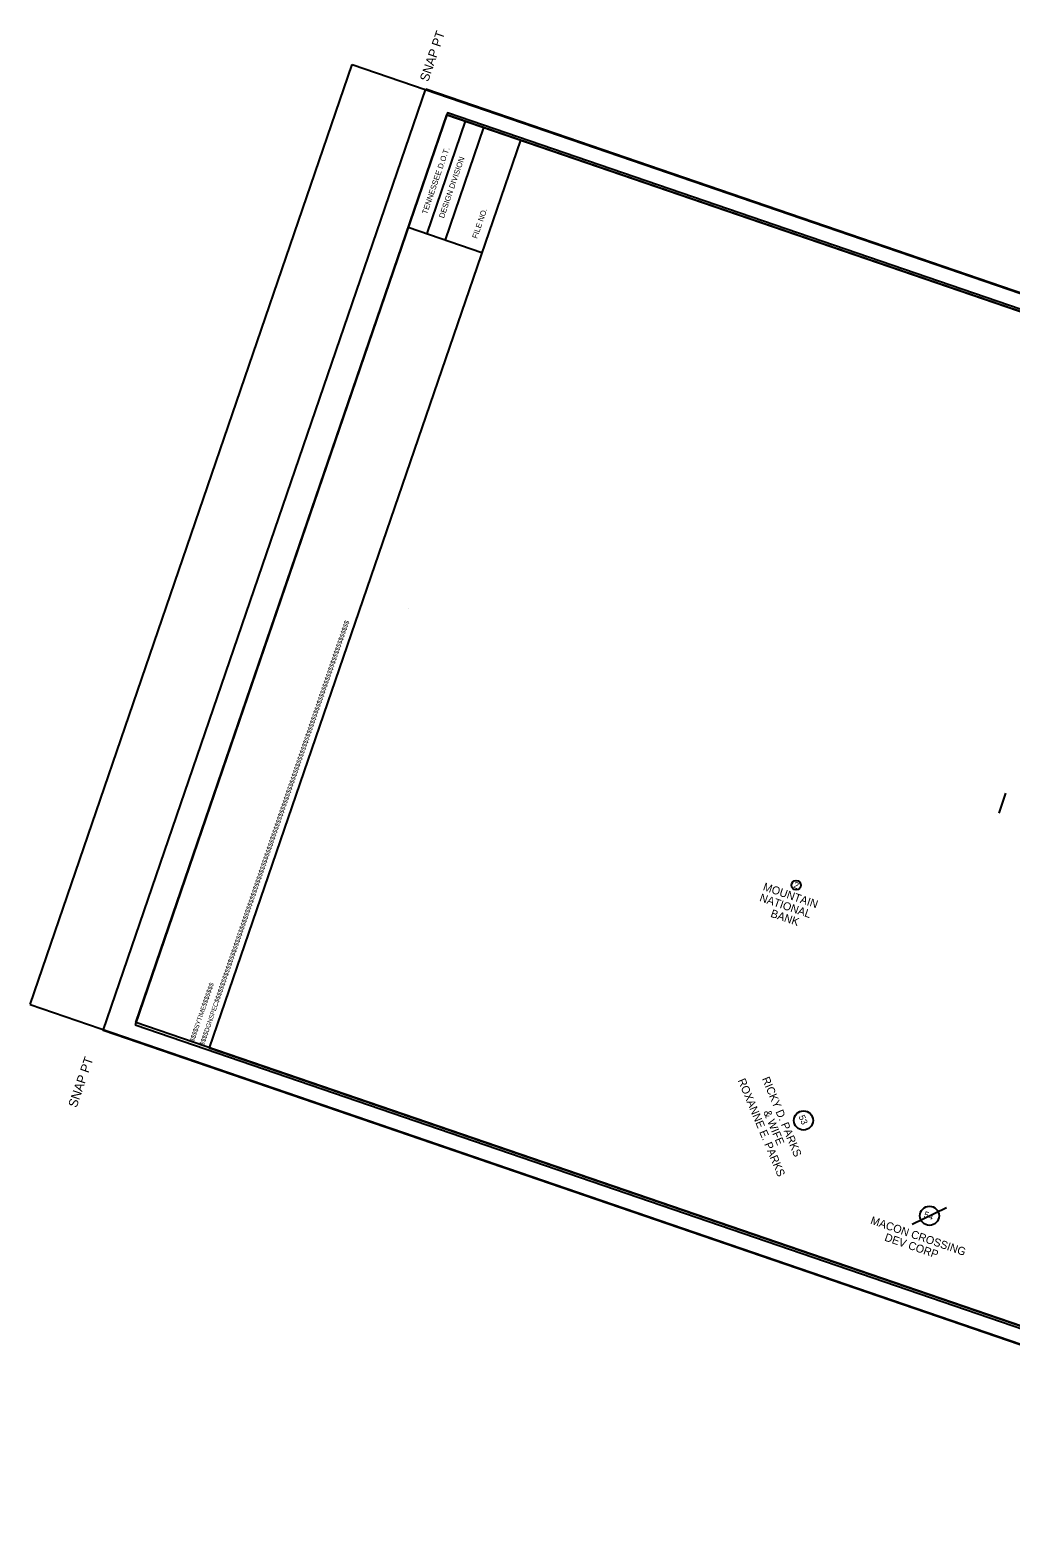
# Model space of a CAD drawing. Extents: x 2626331 to 2628652, y 569305 to 571035.
# Drawn here: x 2626331 to 2627404, y 569386 to 571035 of the extents above; entities that cross this region are included whole.
import ezdxf

# ---------------------------------------------------------------- set-up
doc = ezdxf.new("R2010")
doc.units = 0
for name, color, linetype in [('DESIGN - SCRATCH - User 1', 7, 'Continuous'), ('DESIGN - SHEET - Corner Text', 7, 'Continuous'), ('DESIGN - SHEET - Light Grid', 7, 'Continuous'), ('DESIGN - SHEET - Linework', 7, 'Continuous'), ('DESIGN - SHEET - Plot Shape', 7, 'Continuous'), ('SURVEY - CONTROL with Text', 7, 'Continuous'), ('SURVEY - PROPERTY - Owners', 7, 'Continuous'), ('SURVEY - PROPERTY - Tract Numbers', 7, 'Continuous')]:
    doc.layers.add(name, color=color, linetype=linetype)

msp = doc.modelspace()

# ---------------------------------------------------------------- linework, layer by layer
at = {"layer": 'DESIGN - SCRATCH - User 1'}
msp.add_line((2626744.1, 570402.3), (2626744.1, 570402.3), dxfattribs=at)
at = {"layer": 'DESIGN - SHEET - Light Grid'}
msp.add_lwpolyline([(2626445.3, 569947.1), (2628020.3, 569407.2), (2628362.4, 570405.2), (2626787.4, 570945.1)], close=True, dxfattribs=at)
at = {"layer": 'DESIGN - SHEET - Linework'}
for p, q in [((2626330.5, 569969.3), (2626683.1, 570997.9)), ((2626683.1, 570997.9), (2628385.9, 570414.3)), ((2626806.7, 570935.8), (2626764.5, 570812.9)), ((2626826.8, 570928.9), (2626784.7, 570806)), ((2626330.5, 569969.3), (2628033.2, 569385.6))]:
    msp.add_line(p, q, dxfattribs=at)
for points in [[(2626867, 570915.1), (2626786.5, 570942.7), (2626744.4, 570819.8), (2626824.9, 570792.3)], [(2626867, 570915.1), (2626526.5, 569921.9), (2628015.7, 569411.4), (2628356.1, 570404.7), (2626867, 570915.1)]]:
    msp.add_lwpolyline(points, dxfattribs=at)
at = {"layer": 'DESIGN - SHEET - Plot Shape'}
for points in [[(2626763.7, 570971.4), (2628371.8, 570420.1), (2628018.6, 569389.6), (2626410.4, 569940.8)], [(2626786.5, 570942.7), (2628356.1, 570404.7), (2628015.7, 569411.4), (2626446.1, 569949.5)]]:
    msp.add_lwpolyline(points, close=True, dxfattribs=at)
at = {"layer": 'SURVEY - CONTROL with Text'}
msp.add_line((2627390.9, 570178.5), (2627398.4, 570200.4), dxfattribs=at)
at = {"layer": 'SURVEY - PROPERTY - Tract Numbers'}
msp.add_line((2627295.9, 569728.7), (2627333.6, 569747.2), dxfattribs=at)
for centre, radius in [((2627168.9, 570099.8), 5.25), ((2627176.9, 569842.4), 10.5), ((2627314.8, 569738), 10.5)]:
    msp.add_circle(centre, radius, dxfattribs=at)

# ---------------------------------------------------------------- texts
at = {"layer": 'DESIGN - SHEET - Corner Text'}
for s, height, p in [('  SNAP PT', 10, (2626763.7, 570971.4)), ('TENNESSEE D.O.T.', 6, (2626764.8, 570833.5)), ('DESIGN DIVISION', 6, (2626783.3, 570829.2)), ('FILE NO.', 6, (2626819.7, 570806.8)), ('$$$$DGNSPEC$$$$$$$$$$$$$$$$$$$$$$$$$$$$$$$$$$$$$$$$$$$$$$$$$$$$$$$$$$$$$$$$$$$$$$$$$$$$$$$$$$$$$$$$$$$$$$$$$$$$$$$$$$$$$$$$$$$', 5.0001, (2626520.6, 569923.9)), ('$$$$SYTIME$$$$$$$', 5, (2626509.6, 569927.7)), ('SNAP PT  ', 10, (2626381.3, 569855.7))]:
    msp.add_text(s, height=height, rotation=71.0785, dxfattribs=at).set_placement(p)
at = {"layer": 'SURVEY - PROPERTY - Owners'}
for s, rotation, p in [('MOUNTAIN', 341.0785, (2627131.9, 570094.6)), ('NATIONAL', 341.0785, (2627128.1, 570082.7)), ('BANK', 341.0785, (2627140.2, 570065.4)), ('ROXANNE E. PARKS', 292.6154, (2627104.8, 569886.2)), ('RICKY D. PARKS', 292.6154, (2627131.2, 569888)), ('& WIFE', 292.6154, (2627132.8, 569851.6)), ('MACON CROSSING', 341.0785, (2627249.5, 569729.5)), ('DEV CORP ', 341.0785, (2627264.9, 569711))]:
    msp.add_text(s, height=8.75, rotation=rotation, dxfattribs=at).set_placement(p)
at = {"layer": 'SURVEY - PROPERTY - Tract Numbers'}
for s, rotation, p in [('2', 341.0785, (2627165.4, 570097.3)), ('53', 292.6154, (2627171.4, 569846.6)), ('54', 341.0785, (2627307.9, 569736.6))]:
    msp.add_text(s, height=7, rotation=rotation, dxfattribs=at).set_placement(p)

doc.saveas('drawing.dxf')
